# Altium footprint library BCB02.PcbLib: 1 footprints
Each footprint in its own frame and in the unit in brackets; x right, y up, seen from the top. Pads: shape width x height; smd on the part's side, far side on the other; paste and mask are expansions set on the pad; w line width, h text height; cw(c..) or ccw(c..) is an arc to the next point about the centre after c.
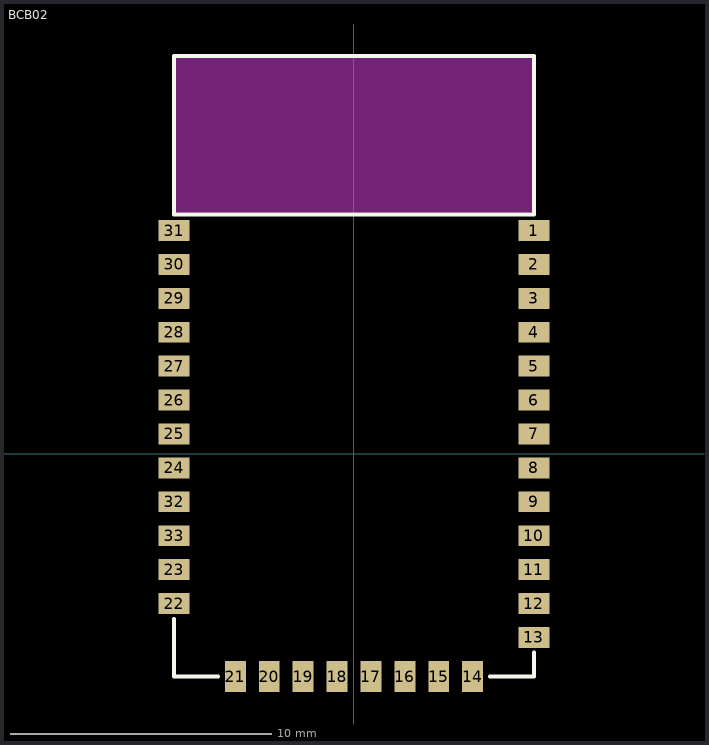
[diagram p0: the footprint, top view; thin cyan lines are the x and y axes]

## BCB02 [mm]
pads (33):
  rect 1.2x0.8 smd: 1(6.9,8.55) 2(6.9,7.25) 3(6.9,5.95) 4(6.9,4.65) 5(6.9,3.35) 6(6.9,2.05) 7(6.9,0.75) 8(6.9,-0.55) 9(6.9,-1.85) 10(6.9,-3.15) 11(6.9,-4.45) 12(6.9,-5.75) 13(6.9,-7.05) 22(-6.9,-5.75) 23(-6.9,-4.45) 24(-6.9,-0.55) 25(-6.9,0.75) 26(-6.9,2.05) 27(-6.9,3.35) 28(-6.9,4.65) 29(-6.9,5.95) 30(-6.9,7.25) 31(-6.9,8.55) 32(-6.9,-1.85) 33(-6.9,-3.15)
  rect 0.8x1.2 smd: 14(4.55,-8.55) 15(3.25,-8.55) 16(1.95,-8.55) 17(0.65,-8.55) 18(-0.65,-8.55) 19(-1.95,-8.55) 20(-3.25,-8.55) 21(-4.55,-8.55)
Top Overlay:
  lines w0.15: -6.9,-6.35 -6.9,-8.55 -5.207,-8.55 ; 5.207,-8.55 6.9,-8.55 6.9,-7.62 ; -6.9,9.162 6.9,9.162 6.9,15.25 -6.9,15.25 -6.9,9.162
Keep-Out Layer:
  pour cut-out: -6.9,15.25 -6.9,9.25 6.9,9.25 6.9,15.25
